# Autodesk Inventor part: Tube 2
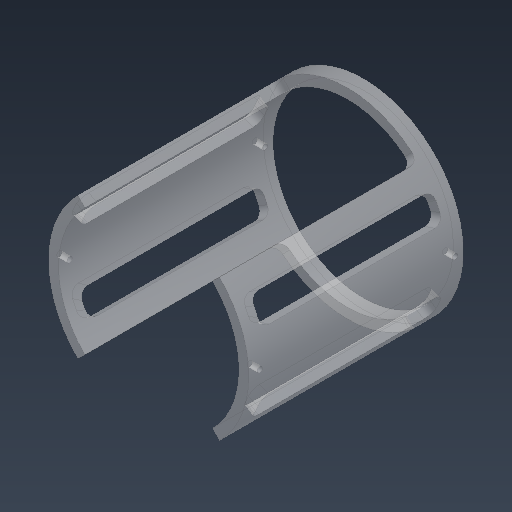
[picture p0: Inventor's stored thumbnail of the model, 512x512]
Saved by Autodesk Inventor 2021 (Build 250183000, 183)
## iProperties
Created: 2020-01
Part Number: Tube 2
Material: SOLIDWORKS Materials|Perspex (TM) GS Acrylic Cast Sheet
Document SubType Name: Modeling
Designer: ftrauzettel
Density: 1.19 g/cm^3
Appearance: 219,219,219
Author: ftrauzettel
Sending System: SolidWorks 2016
Last Author: Pam
Last Saved: 2020-07-21
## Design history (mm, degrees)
fillet "Fillet1"
body "Solid1"
